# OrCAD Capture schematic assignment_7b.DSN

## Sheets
1 PAGE1: size A
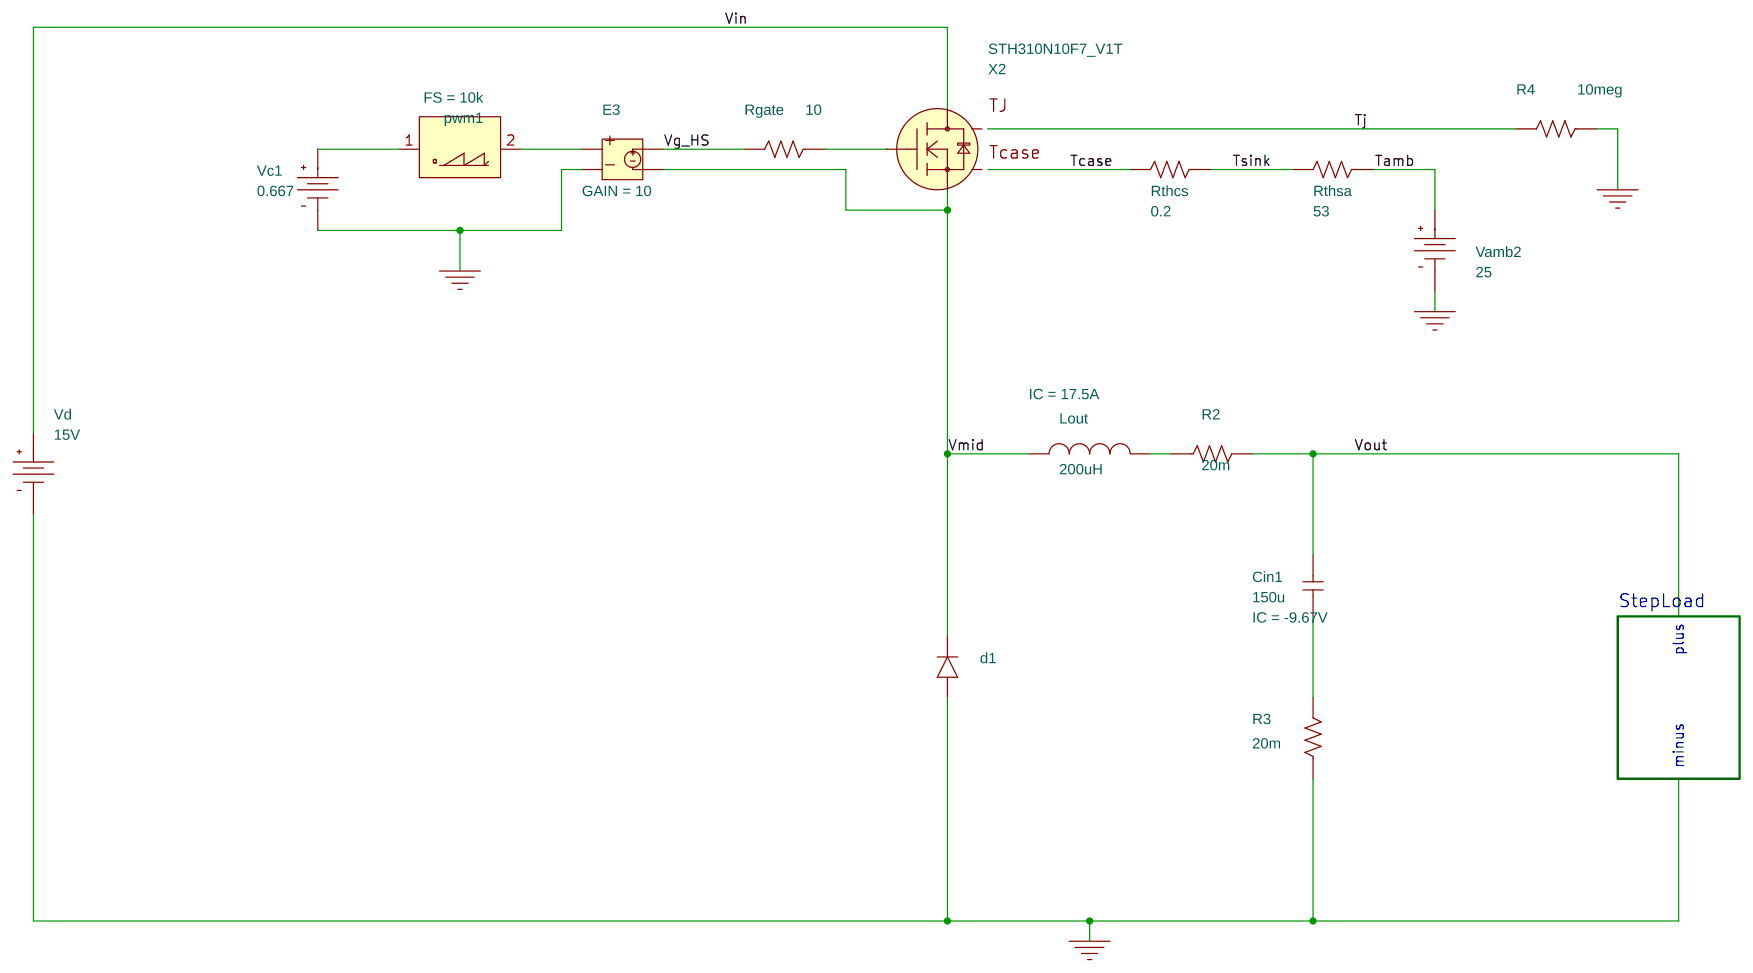
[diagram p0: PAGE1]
2 PAGE1 (2): size A; block StepLoad
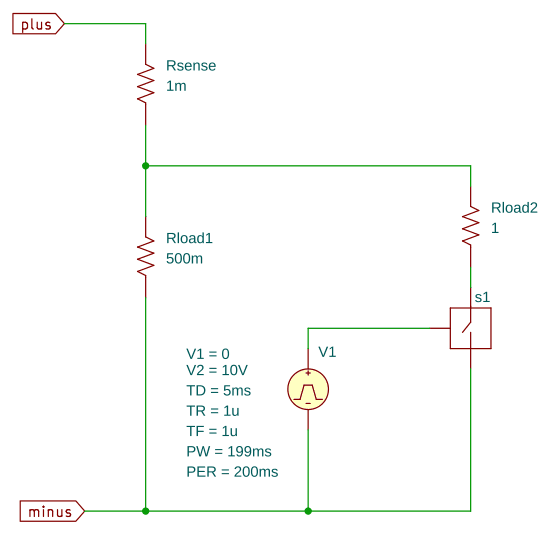
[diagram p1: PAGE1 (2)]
3 PAGE1 (3)
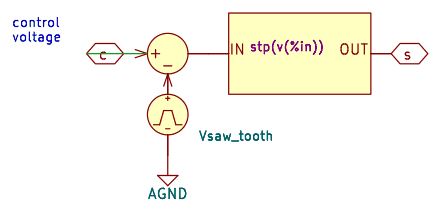
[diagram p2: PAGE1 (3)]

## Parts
sheet PAGE1 (2)
Rload1  500m  [AX/RC05]
Rload2  1  [AX/RC05]
Rsense  1m  [AX/RC05]
s1  s
V1  VPULSE
sheet PAGE1 (3)
ABM13  abm1
DIFF1  diff
Vsaw_tooth  VPULSE
sheet PAGE1
Cin1  150u  [RAD/CK05]
d1  d
E3  E
Lout  200uH  [L3216C]
pwm1  PWM_ST
R2  20m  [AX/RC05]
R3  20m  [AX/RC05]
R4  10meg  [AX/RC05]
Rgate  10  [AX/RC05]
Rthcs  0.2  [AX/RC05]
Rthsa  53  [AX/RC05]
Vamb2  VDC
Vc1  VDC
Vd  VDC
X2  STH310N10F7_V1T

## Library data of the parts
R2-R4 Rgate Rload1 Rload2 Rsense Rthcs Rthsa = R
s1 = v-switch
V1 = VPULSE: PER: 200ms; PW: 199ms; TD: 5ms; TF: 1u; TR: 1u; V1: 0; V2: 10V
ABM13 = ABM1: EXP1: stp(v(%in))
DIFF1 = DIFF_v2
Vsaw_tooth = VPULSE: PER: {1/@FS}; PW: 0.01us; TD: 0; TF: 0.01us; TR: {1/@FS - 0.02us}; V1: 0V; V2: 1V
Cin1 = C: IC: -9.67V
d1 = diode
E3 = E: GAIN: 10
Lout = L: IC: 17.5A
pwm1 = PWM_ST: FS: 10k
Vamb2 = VDC: DC: 25
Vc1 = VDC: DC: 0.667
Vd = VDC: DC: 15V
X2 = STH310N10F7_V1T

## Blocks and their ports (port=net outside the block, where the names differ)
StepLoad = schematic Load2, on sheet PAGE1: minus=0, plus=Vout

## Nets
AGND: Vsaw_tooth.2(-)
Vin: Vd.0(+) X2.1
0: d1.1(A) E3.2 R3.1 R4.1 Rload1.1 s1.3(s-) V1.2(-) Vamb2.1(-) Vc1.1(-) Vd.1(-)
c: DIFF1.3(IN2)
s: ABM13.2(OUT)
Tamb: Rthsa.1 Vamb2.0(+)
Tcase: Rthcs.2 X2.Tcase
Tj: R4.2 X2.Tj
Tsink: Rthcs.1 Rthsa.2
Vg_HS: E3.3 Rgate.2
Vmid: d1.2(K) E3.4 Lout.1 X2.3
Vout: Cin1.2 R2.2 Rsense.2
N42809: E3.1 pwm1.2(s)
N42915: Rgate.1 X2.2
N43035: Cin1.1 R3.2
N43045: pwm1.1(c) Vc1.0(+)
N43213: Lout.2 R2.1
StepLoad/N03583: Rload1.2 Rload2.2 Rsense.1
StepLoad/N03605: s1.1(vc+) V1.1(+)
StepLoad/N03791: Rload2.1 s1.2(s+)

Not connected (* = marked no-connect by the designer): ABM13 1(IN); DIFF1 1(IN1) 5(OUT); Vsaw_tooth 1(+)

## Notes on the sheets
sheet 3
- control
  voltage
